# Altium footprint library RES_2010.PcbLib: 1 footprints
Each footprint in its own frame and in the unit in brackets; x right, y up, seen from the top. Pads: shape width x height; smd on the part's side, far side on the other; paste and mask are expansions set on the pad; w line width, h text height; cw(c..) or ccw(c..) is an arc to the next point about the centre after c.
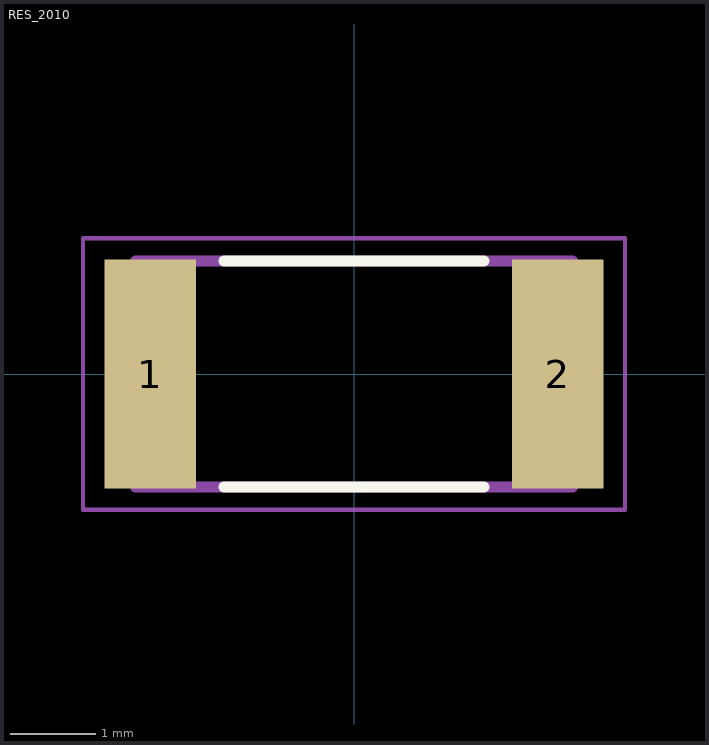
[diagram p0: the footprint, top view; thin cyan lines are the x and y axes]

## RES_2010 [mm]
pads (2):
  rect 1.07x2.67 smd: 1(-2.38,0) 2(2.38,0)
Top Overlay:
  lines w0.127: -1.52,-1.32 1.52,-1.32 ; -1.52,1.32 1.52,1.32
Mechanical 13:
  lines w0.127: -2.55,-1.32 2.55,-1.32 2.55,1.32 -2.55,1.32 -2.55,-1.32
Mechanical 15:
  lines w0.05: -3.165,-1.585 3.165,-1.585 3.165,1.585 -3.165,1.585 -3.165,-1.585
3D body "RES_2010.STEP": height 1.2, standoff 0, extent -2.5,-1.25 2.5,1.25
